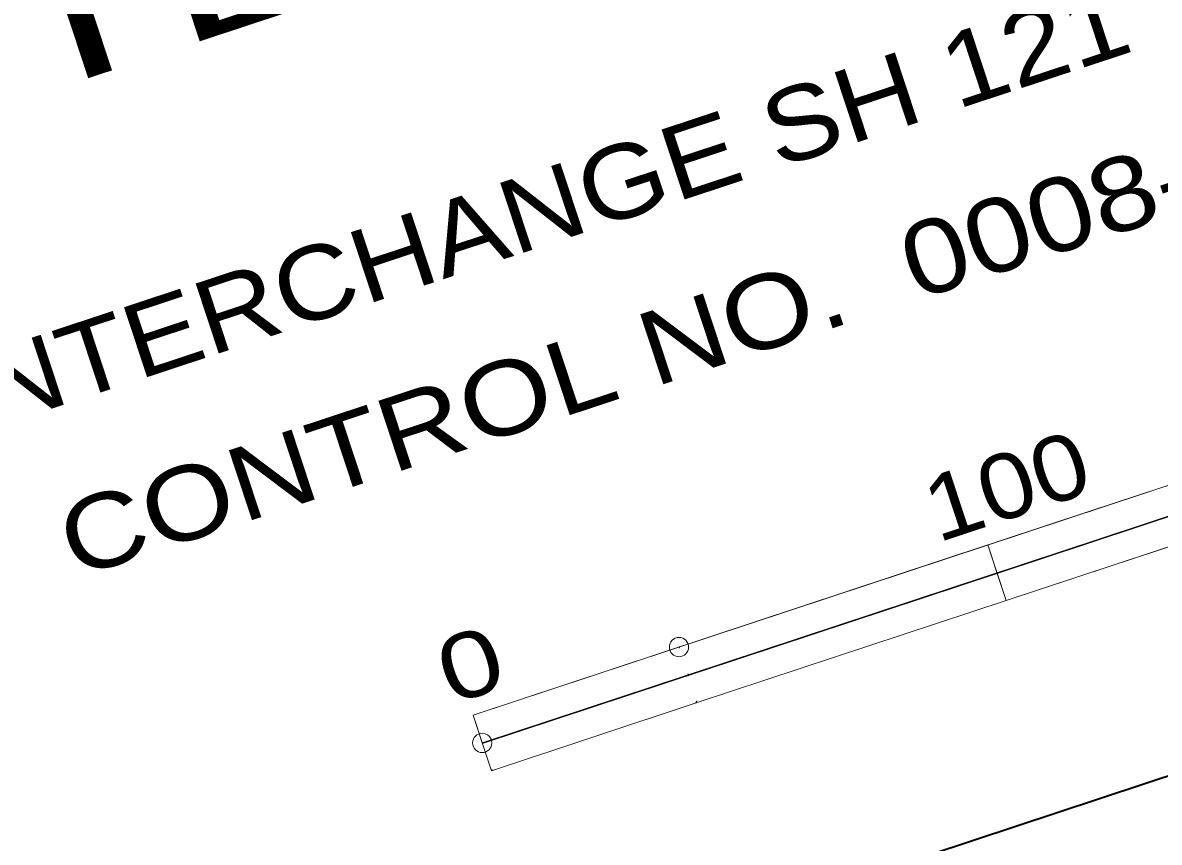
# Model space of a CAD drawing. Extents: x 2355803 to 2371254, y 6970215 to 6985302.
# Drawn here: x 2357035 to 2357244.6, y 6973991.6 to 6974142.6 of the extents above; entities that cross this region are included whole.
import ezdxf

# ---------------------------------------------------------------- set-up
doc = ezdxf.new("R2010")
doc.units = 0
doc.header["$LTSCALE"] = 7.1
doc.header["$PDMODE"] = 32
doc.header["$PDSIZE"] = 3.55
doc.layers.add('19', color=7, linetype='Continuous', lineweight=13)
doc.layers.add('8', color=7, linetype='Continuous', lineweight=13)

msp = doc.modelspace()

# ---------------------------------------------------------------- linework, layer by layer
at = {"layer": '19', "lineweight": 35}
msp.add_line((2357566.598, 6974109.603), (2356800.078, 6973856.379), dxfattribs=at)
at = {"layer": '19'}
for p, q in [((2357118.063, 6974014.995), (2357307.971, 6974077.733)), ((2357232.008, 6974052.637), (2357307.971, 6974077.733)), ((2357311.355, 6974067.489), (2357235.391, 6974042.394)), ((2357156.045, 6974027.543), (2357232.008, 6974052.637)), ((2357231.966, 6974052.623), (2357232.022, 6974052.595)), ((2357233.699, 6974047.516), (2357157.737, 6974022.421)), ((2357213.017, 6974046.364), (2357216.401, 6974036.121)), ((2357159.429, 6974017.3), (2357235.391, 6974042.394)), ((2357118.063, 6974014.995), (2357156.045, 6974027.543)), ((2357156.074, 6974027.457), (2357156.131, 6974027.571)), ((2357156.103, 6974027.368), (2357156.22, 6974027.6)), ((2357119.756, 6974009.874), (2357157.737, 6974022.421)), ((2357157.577, 6974022.368), (2357157.791, 6974022.261)), ((2357157.665, 6974022.398), (2357157.76, 6974022.35)), ((2357157.67, 6974022.624), (2357157.94, 6974022.488)), ((2357157.699, 6974022.535), (2357157.85, 6974022.459)), ((2357157.729, 6974022.446), (2357157.761, 6974022.429)), ((2357159.107, 6974017.193), (2357159.323, 6974017.622)), ((2357159.196, 6974017.223), (2357159.352, 6974017.532)), ((2357119.756, 6974009.874), (2357118.063, 6974014.995)), ((2357119.781, 6974009.796), (2357119.834, 6974009.899)), ((2357119.812, 6974009.706), (2357119.923, 6974009.929)), ((2357121.368, 6974004.992), (2357121.687, 6974004.831)), ((2357121.398, 6974004.902), (2357121.597, 6974004.802))]:
    msp.add_line(p, q, dxfattribs=at)
for points in [[(2357214.764, 6974041.139), (2357309.699, 6974072.501), (2357311.355, 6974067.489), (2357216.419, 6974036.127)], [(2357118.063, 6974014.995), (2357213.036, 6974046.37), (2357214.764, 6974041.139), (2357119.791, 6974009.765)]]:
    msp.add_lwpolyline(points, close=True, dxfattribs=at)
for points in [[(2357233.699, 6974047.516), (2357309.663, 6974072.611), (2357311.355, 6974067.489)], [(2357159.429, 6974017.3), (2357121.447, 6974004.752), (2357119.756, 6974009.874)]]:
    msp.add_lwpolyline(points, dxfattribs=at)
for p in [(2357156.045, 6974027.543), (2357119.756, 6974009.874)]:
    msp.add_point(p, dxfattribs=at)
at = {"layer": '8', "lineweight": 35}
msp.add_line((2357566.598, 6974109.603), (2356800.078, 6973856.379), dxfattribs=at)
at = {"layer": '8'}
for p, q in [((2357118.063, 6974014.995), (2357307.971, 6974077.733)), ((2357232.008, 6974052.637), (2357307.971, 6974077.733)), ((2357311.355, 6974067.489), (2357235.391, 6974042.394)), ((2357156.045, 6974027.543), (2357232.008, 6974052.637)), ((2357231.966, 6974052.623), (2357232.022, 6974052.595)), ((2357233.699, 6974047.516), (2357157.737, 6974022.421)), ((2357213.017, 6974046.364), (2357216.401, 6974036.121)), ((2357159.429, 6974017.3), (2357235.391, 6974042.394)), ((2357118.063, 6974014.995), (2357156.045, 6974027.543)), ((2357156.074, 6974027.457), (2357156.131, 6974027.571)), ((2357156.103, 6974027.368), (2357156.22, 6974027.6)), ((2357119.756, 6974009.874), (2357157.737, 6974022.421)), ((2357157.577, 6974022.368), (2357157.791, 6974022.261)), ((2357157.665, 6974022.398), (2357157.76, 6974022.35)), ((2357157.67, 6974022.624), (2357157.94, 6974022.488)), ((2357157.699, 6974022.535), (2357157.85, 6974022.459)), ((2357157.729, 6974022.446), (2357157.761, 6974022.429)), ((2357159.107, 6974017.193), (2357159.323, 6974017.622)), ((2357159.196, 6974017.223), (2357159.352, 6974017.532)), ((2357119.756, 6974009.874), (2357118.063, 6974014.995)), ((2357119.781, 6974009.796), (2357119.834, 6974009.899)), ((2357119.812, 6974009.706), (2357119.923, 6974009.929)), ((2357121.368, 6974004.992), (2357121.687, 6974004.831)), ((2357121.398, 6974004.902), (2357121.597, 6974004.802))]:
    msp.add_line(p, q, dxfattribs=at)
for points in [[(2357214.764, 6974041.139), (2357309.699, 6974072.501), (2357311.355, 6974067.489), (2357216.419, 6974036.127)], [(2357118.063, 6974014.995), (2357213.036, 6974046.37), (2357214.764, 6974041.139), (2357119.791, 6974009.765)]]:
    msp.add_lwpolyline(points, close=True, dxfattribs=at)
for points in [[(2357233.699, 6974047.516), (2357309.663, 6974072.611), (2357311.355, 6974067.489)], [(2357159.429, 6974017.3), (2357121.447, 6974004.752), (2357119.756, 6974009.874)]]:
    msp.add_lwpolyline(points, dxfattribs=at)
for p in [(2357156.045, 6974027.543), (2357119.756, 6974009.874)]:
    msp.add_point(p, dxfattribs=at)

# ---------------------------------------------------------------- texts
at = {"layer": '19'}
for s, height, width, p in [(' HOV ALTERNATIVE 5A', 23.33, 1.6, (2356847.786, 6974066.579)), ('LIMITS:  NORTH INTERCHANGE SH 121 TO RANDOL MILL ROAD', 13.58, 1.15, (2356867.926, 6974014.529)), ('CONTROL NO.  0008-13-123', 13.58, 1.2, (2357044.55, 6974040.119)), ('100', 12, 1.15, (2357203.747, 6974046.747)), ('0', 12, 1.3, (2357113.942, 6974016.836))]:
    msp.add_text(s, height=height, rotation=18.281, dxfattribs=dict(at, width=width)).set_placement(p)
at = {"layer": '8'}
for s, height, width, p in [(' HOV ALTERNATIVE 5A', 23.33, 1.6, (2356847.786, 6974066.579)), ('LIMITS:  NORTH INTERCHANGE SH 121 TO RANDOL MILL ROAD', 13.58, 1.15, (2356867.926, 6974014.529)), ('CONTROL NO.  0008-13-123', 13.58, 1.2, (2357044.55, 6974040.119)), ('100', 12, 1.15, (2357203.747, 6974046.747)), ('0', 12, 1.3, (2357113.942, 6974016.836))]:
    msp.add_text(s, height=height, rotation=18.281, dxfattribs=dict(at, width=width)).set_placement(p)

doc.saveas('drawing.dxf')
